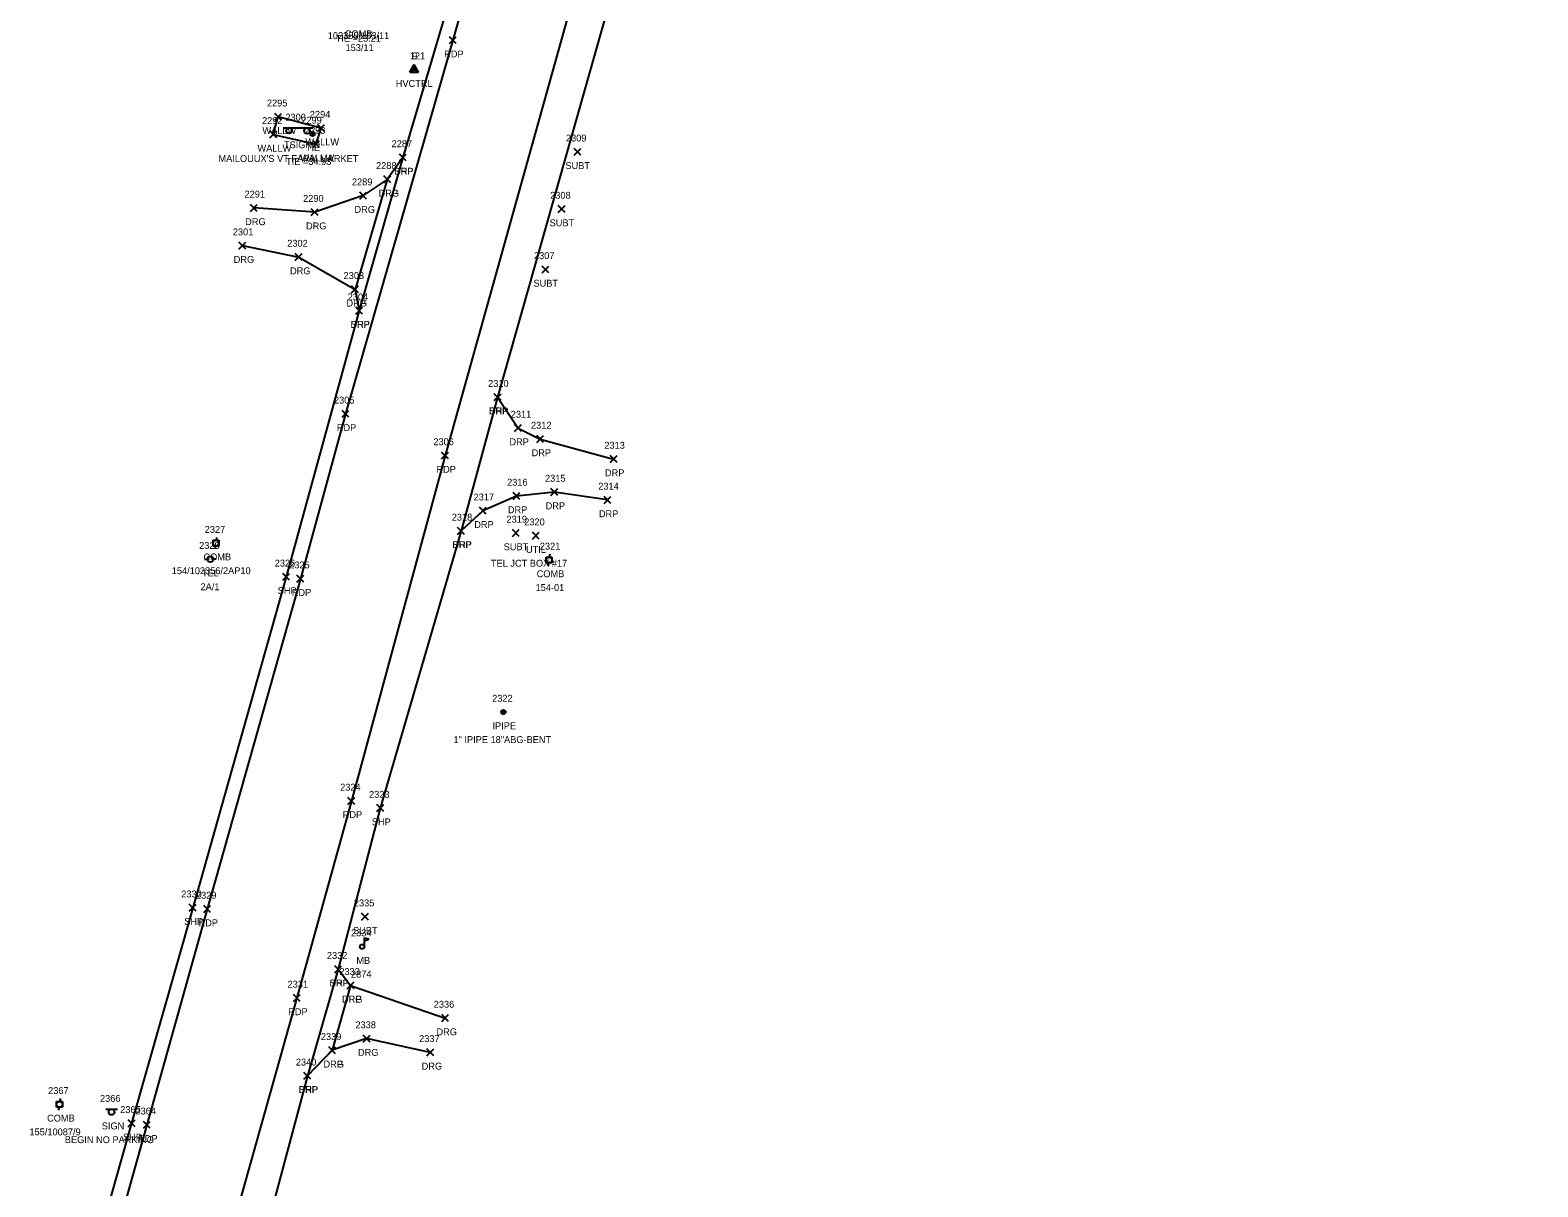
# Model space of a CAD drawing. Extents: x 1443071 to 1445292, y 614024 to 622563.
# Drawn here: x 1444316.5 to 1444754.4, y 621220.7 to 621556.7 of the extents above; entities that cross this region are included whole.
import ezdxf

# ---------------------------------------------------------------- set-up
doc = ezdxf.new("R2010")
doc.units = 0
for name, color, linetype in [('C_A', 7, 'Continuous'), ('C_C', 7, 'Continuous'), ('C_I', 7, 'Continuous'), ('CBP', 7, 'Continuous'), ('CPSM', 7, 'Continuous'), ('L_A', 7, 'Continuous'), ('L_C', 7, 'Continuous'), ('L_I', 7, 'Continuous'), ('L_TIC', 7, 'Continuous'), ('LMB', 7, 'Continuous'), ('LW', 7, 'Continuous'), ('M_A', 7, 'Continuous'), ('M_C', 7, 'Continuous'), ('M_I', 7, 'Continuous'), ('MPIP', 7, 'Continuous'), ('P_A', 7, 'Continuous'), ('P_I', 7, 'Continuous'), ('P_TIC', 7, 'Continuous'), ('PET', 7, 'Continuous'), ('PSP', 7, 'Continuous'), ('R_A', 7, 'Continuous'), ('R_I', 7, 'Continuous'), ('R_TIC', 7, 'Continuous'), ('RDG', 7, 'Continuous'), ('RDP', 7, 'Continuous'), ('S_A', 7, 'Continuous'), ('S_C', 7, 'Continuous'), ('S_I', 7, 'Continuous'), ('SSGN', 7, 'Continuous'), ('U_A', 7, 'Continuous'), ('U_C', 7, 'Continuous'), ('U_I', 7, 'Continuous'), ('U_TIC', 7, 'Continuous'), ('UDEFAULT', 7, 'Continuous'), ('UP', 7, 'Continuous')]:
    doc.layers.add(name, color=color, linetype=linetype)

msp = doc.modelspace()

# ---------------------------------------------------------------- linework, layer by layer
at = {"layer": 'CBP'}
for radius in [0.625, 0.0833]:
    msp.add_circle((1444398.54, 621526.59), radius, dxfattribs=at)
at = {"layer": 'CPSM'}
for p, q in [((1444426.77, 621544.56), (1444428.02, 621546.72)), ((1444426.77, 621544.56), (1444428.02, 621545.28)), ((1444426.8, 621544.55), (1444428.05, 621546.72)), ((1444426.8, 621544.55), (1444428.05, 621545.27)), ((1444429.27, 621544.56), (1444428.02, 621546.72)), ((1444428.02, 621545.28), (1444428.02, 621546.72)), ((1444428.02, 621545.28), (1444428.02, 621545.28)), ((1444428.02, 621545.28), (1444429.27, 621544.56)), ((1444429.3, 621544.55), (1444428.05, 621546.72)), ((1444428.05, 621545.27), (1444428.05, 621546.72)), ((1444428.05, 621545.27), (1444428.05, 621545.27)), ((1444428.05, 621545.27), (1444429.3, 621544.55)), ((1444426.77, 621544.56), (1444429.27, 621544.56)), ((1444426.8, 621544.55), (1444429.3, 621544.55))]:
    msp.add_line(p, q, dxfattribs=at)
at = {"layer": 'L_TIC'}
for points in [[(1444387.57, 621530.57), (1444389.57, 621532.57)], [(1444389.57, 621530.57), (1444387.57, 621532.57)], [(1444387.57, 621530.57), (1444389.57, 621532.57)], [(1444389.57, 621530.57), (1444387.57, 621532.57)], [(1444386.14, 621525.46), (1444388.14, 621527.46)], [(1444388.14, 621525.46), (1444386.14, 621527.46)], [(1444386.14, 621525.46), (1444388.14, 621527.46)], [(1444388.14, 621525.46), (1444386.14, 621527.46)], [(1444400.03, 621527.29), (1444402.03, 621529.29)], [(1444402.03, 621527.29), (1444400.03, 621529.29)], [(1444398.59, 621522.64), (1444400.59, 621524.64)], [(1444400.59, 621522.64), (1444398.59, 621524.64)]]:
    msp.add_lwpolyline(points, dxfattribs=at)
at = {"layer": 'LMB'}
for p, q in [((1444413.63, 621293.12), (1444414.92, 621292.74)), ((1444413.63, 621290.53), (1444413.63, 621293.12)), ((1444413.63, 621292.22), (1444414.91, 621292.73)), ((1444412.98, 621290.52), (1444412.98, 621290.52))]:
    msp.add_line(p, q, dxfattribs=at)
msp.add_circle((1444412.98, 621290.52), 0.656, dxfattribs=at)
at = {"layer": 'LW'}
for points in [[(1444387.14, 621526.46), (1444399.59, 621523.64), (1444401.03, 621528.29), (1444388.57, 621531.57)], [(1444387.14, 621526.46), (1444388.57, 621531.57)]]:
    msp.add_lwpolyline(points, dxfattribs=at)
at = {"layer": 'MPIP'}
for radius in [0.625, 0.0833]:
    msp.add_circle((1444453.98, 621358.66), radius, dxfattribs=at)
at = {"layer": 'P_TIC'}
for points in [[(1444438.29, 621552.82), (1444440.29, 621554.82)], [(1444440.29, 621552.82), (1444438.29, 621554.82)], [(1444423.77, 621518.75), (1444425.77, 621520.75)], [(1444425.77, 621518.75), (1444423.77, 621520.75)], [(1444411.09, 621474.26), (1444413.09, 621476.26)], [(1444413.09, 621474.26), (1444411.09, 621476.26)], [(1444451.32, 621449.13), (1444453.32, 621451.13)], [(1444453.32, 621449.13), (1444451.32, 621451.13)], [(1444407.11, 621444.28), (1444409.11, 621446.28)], [(1444409.11, 621444.28), (1444407.11, 621446.28)], [(1444436.04, 621432.18), (1444438.04, 621434.18)], [(1444438.04, 621432.18), (1444436.04, 621434.18)], [(1444440.68, 621410.27), (1444442.68, 621412.27)], [(1444442.68, 621410.27), (1444440.68, 621412.27)], [(1444389.88, 621396.93), (1444391.88, 621398.93)], [(1444391.88, 621396.93), (1444389.88, 621398.93)], [(1444394.03, 621396.39), (1444396.03, 621398.39)], [(1444396.03, 621396.39), (1444394.03, 621398.39)], [(1444408.83, 621331.84), (1444410.83, 621333.84)], [(1444410.83, 621331.84), (1444408.83, 621333.84)], [(1444417.22, 621329.76), (1444419.22, 621331.76)], [(1444419.22, 621329.76), (1444417.22, 621331.76)], [(1444362.76, 621300.82), (1444364.76, 621302.82)], [(1444364.76, 621300.82), (1444362.76, 621302.82)], [(1444366.96, 621300.44), (1444368.96, 621302.44)], [(1444368.96, 621300.44), (1444366.96, 621302.44)], [(1444404.98, 621282.95), (1444406.98, 621284.95)], [(1444406.98, 621282.95), (1444404.98, 621284.95)], [(1444392.99, 621274.61), (1444394.99, 621276.61)], [(1444394.99, 621274.61), (1444392.99, 621276.61)], [(1444396.04, 621251.99), (1444398.04, 621253.99)], [(1444398.04, 621251.99), (1444396.04, 621253.99)], [(1444344.99, 621238.2), (1444346.99, 621240.2)], [(1444346.99, 621238.2), (1444344.99, 621240.2)], [(1444349.41, 621237.76), (1444351.41, 621239.76)], [(1444351.41, 621237.76), (1444349.41, 621239.76)]]:
    msp.add_lwpolyline(points, dxfattribs=at)
at = {"layer": 'PET'}
for points in [[(1444754.44, 622544.13), (1444741.07, 622497.37), (1444724.21, 622436.63), (1444710.62, 622388.87), (1444697.45, 622342.15), (1444675, 622264.13), (1444650.85, 622183.92), (1444630.28, 622116), (1444610.88, 622049.25), (1444594.96, 621996.24), (1444563.37, 621884.27), (1444533.4, 621779.05), (1444495.09, 621640.86), (1444437.04, 621433.18), (1444409.83, 621332.84), (1444393.99, 621275.61), (1444360.23, 621155.32)], [(1444707.59, 622509.11), (1444700.19, 622484.07), (1444679.05, 622409.28), (1444655.77, 622327.83), (1444650.07, 622306.66), (1444636.13, 622255.68), (1444623.55, 622208.8), (1444606.26, 622146.53), (1444595.29, 622106.04), (1444582.56, 622060.23), (1444534.43, 621893.79), (1444481.57, 621704.27), (1444439.29, 621553.82), (1444408.11, 621445.28), (1444395.03, 621397.39), (1444367.96, 621301.44), (1444350.41, 621238.76), (1444319.14, 621126.97)]]:
    msp.add_lwpolyline(points, dxfattribs=at)
at = {"layer": 'PSP'}
for points in [[(1444703.05, 622509.58), (1444696.35, 622485.04), (1444679.96, 622426.95), (1444670.67, 622398.4), (1444651.65, 622328.99), (1444645.77, 622309.01), (1444600.31, 622147.99), (1444589.19, 622108.06), (1444575.49, 622063.15), (1444529.28, 621895.39), (1444476.53, 621706.36), (1444455.46, 621630.82), (1444442.09, 621578.45), (1444424.77, 621519.75), (1444412.09, 621475.26), (1444390.88, 621397.93), (1444363.76, 621301.82), (1444345.99, 621239.2), (1444324.65, 621163.68)], [(1444745.15, 622495.54), (1444738.65, 622472.69), (1444728.21, 622436.2), (1444714.89, 622387.13), (1444701.45, 622339.69), (1444679.77, 622260.17), (1444671.12, 622229.57), (1444657.52, 622182.26), (1444644.19, 622133.53), (1444626.95, 622072.43), (1444608.5, 622007.83), (1444599.1, 621977.5), (1444572.99, 621881.76), (1444551.74, 621805.05), (1444541.41, 621769.53), (1444519.46, 621688.51), (1444505.68, 621638.77), (1444452.32, 621450.13), (1444441.68, 621411.27), (1444418.22, 621330.76), (1444405.98, 621283.95), (1444397.04, 621252.99), (1444383.69, 621203.04)]]:
    msp.add_lwpolyline(points, dxfattribs=at)
at = {"layer": 'R_TIC'}
for points in [[(1444423.77, 621518.75), (1444425.77, 621520.75)], [(1444425.77, 621518.75), (1444423.77, 621520.75)], [(1444419.25, 621512.39), (1444421.25, 621514.39)], [(1444421.25, 621512.39), (1444419.25, 621514.39)], [(1444419.25, 621512.39), (1444421.25, 621514.39)], [(1444421.25, 621512.39), (1444419.25, 621514.39)], [(1444380.49, 621504.1), (1444382.49, 621506.1)], [(1444382.49, 621504.1), (1444380.49, 621506.1)], [(1444412.25, 621507.67), (1444414.25, 621509.67)], [(1444414.25, 621507.67), (1444412.25, 621509.67)], [(1444398.17, 621502.87), (1444400.17, 621504.87)], [(1444400.17, 621502.87), (1444398.17, 621504.87)], [(1444377.17, 621493.14), (1444379.17, 621495.14)], [(1444379.17, 621493.14), (1444377.17, 621495.14)], [(1444393.54, 621489.83), (1444395.54, 621491.83)], [(1444395.54, 621489.83), (1444393.54, 621491.83)], [(1444409.91, 621480.45), (1444411.91, 621482.45)], [(1444411.91, 621480.45), (1444409.91, 621482.45)], [(1444409.91, 621480.45), (1444411.91, 621482.45)], [(1444411.91, 621480.45), (1444409.91, 621482.45)], [(1444411.09, 621474.26), (1444413.09, 621476.26)], [(1444413.09, 621474.26), (1444411.09, 621476.26)], [(1444451.32, 621449.13), (1444453.32, 621451.13)], [(1444453.32, 621449.13), (1444451.32, 621451.13)], [(1444457.25, 621440.16), (1444459.25, 621442.16)], [(1444459.25, 621440.16), (1444457.25, 621442.16)], [(1444463.68, 621436.97), (1444465.68, 621438.97)], [(1444465.68, 621436.97), (1444463.68, 621438.97)], [(1444484.99, 621431.15), (1444486.99, 621433.15)], [(1444486.99, 621431.15), (1444484.99, 621433.15)], [(1444456.8, 621420.42), (1444458.8, 621422.42)], [(1444458.8, 621420.42), (1444456.8, 621422.42)], [(1444467.77, 621421.57), (1444469.77, 621423.57)], [(1444469.77, 621421.57), (1444467.77, 621423.57)], [(1444447.02, 621416.13), (1444449.02, 621418.13)], [(1444449.02, 621416.13), (1444447.02, 621418.13)], [(1444483.23, 621419.26), (1444485.23, 621421.26)], [(1444485.23, 621419.26), (1444483.23, 621421.26)], [(1444440.68, 621410.27), (1444442.68, 621412.27)], [(1444442.68, 621410.27), (1444440.68, 621412.27)], [(1444404.98, 621282.95), (1444406.98, 621284.95)], [(1444406.98, 621282.95), (1444404.98, 621284.95)], [(1444408.61, 621278.27), (1444410.61, 621280.27)], [(1444410.61, 621278.27), (1444408.61, 621280.27)], [(1444408.61, 621278.27), (1444410.61, 621280.27)], [(1444410.61, 621278.27), (1444408.61, 621280.27)], [(1444436.06, 621268.77), (1444438.06, 621270.77)], [(1444438.06, 621268.77), (1444436.06, 621270.77)], [(1444413.27, 621262.8), (1444415.27, 621264.8)], [(1444415.27, 621262.8), (1444413.27, 621264.8)], [(1444403.24, 621259.4), (1444405.24, 621261.4)], [(1444405.24, 621259.4), (1444403.24, 621261.4)], [(1444403.24, 621259.4), (1444405.24, 621261.4)], [(1444405.24, 621259.4), (1444403.24, 621261.4)], [(1444431.76, 621258.8), (1444433.76, 621260.8)], [(1444433.76, 621258.8), (1444431.76, 621260.8)], [(1444396.04, 621251.99), (1444398.04, 621253.99)], [(1444398.04, 621251.99), (1444396.04, 621253.99)]]:
    msp.add_lwpolyline(points, dxfattribs=at)
at = {"layer": 'RDG'}
for points in [[(1444420.25, 621513.39), (1444413.25, 621508.67), (1444399.17, 621503.87), (1444381.49, 621505.1)], [(1444378.17, 621494.14), (1444394.54, 621490.83), (1444410.91, 621481.45)], [(1444409.61, 621279.27), (1444437.06, 621269.77)], [(1444432.76, 621259.8), (1444414.27, 621263.8), (1444404.24, 621260.4)]]:
    msp.add_lwpolyline(points, dxfattribs=at)
at = {"layer": 'RDP'}
for points in [[(1444424.77, 621519.75), (1444420.25, 621513.39), (1444410.91, 621481.45), (1444412.09, 621475.26)], [(1444452.32, 621450.13), (1444458.25, 621441.16), (1444464.68, 621437.97), (1444485.99, 621432.15)], [(1444484.23, 621420.26), (1444468.77, 621422.57), (1444457.8, 621421.42), (1444448.02, 621417.13), (1444441.68, 621411.27)], [(1444405.98, 621283.95), (1444409.61, 621279.27), (1444404.24, 621260.4), (1444397.04, 621252.99)]]:
    msp.add_lwpolyline(points, dxfattribs=at)
at = {"layer": 'SSGN'}
for p, q in [((1444390.07, 621528.37), (1444398.66, 621528.37)), ((1444394.09, 621527.47), (1444394.09, 621527.47)), ((1444338.55, 621243.3), (1444341.88, 621243.3)), ((1444340.19, 621242.46), (1444340.19, 621242.46))]:
    msp.add_line(p, q, dxfattribs=at)
for centre in [(1444391.73, 621527.54), (1444396.94, 621527.47), (1444340.19, 621242.46)]:
    msp.add_circle(centre, 0.833, dxfattribs=at)
at = {"layer": 'U_TIC'}
for points in [[(1444474.5, 621520.4), (1444476.5, 621522.4)], [(1444476.5, 621520.4), (1444474.5, 621522.4)], [(1444469.91, 621503.77), (1444471.91, 621505.77)], [(1444471.91, 621503.77), (1444469.91, 621505.77)], [(1444465.21, 621486.23), (1444467.21, 621488.23)], [(1444467.21, 621486.23), (1444465.21, 621488.23)], [(1444456.58, 621409.67), (1444458.58, 621411.67)], [(1444458.58, 621409.67), (1444456.58, 621411.67)], [(1444412.81, 621298.21), (1444414.81, 621300.21)], [(1444414.81, 621298.21), (1444412.81, 621300.21)]]:
    msp.add_lwpolyline(points, dxfattribs=at)
at = {"layer": 'UDEFAULT'}
for points in [[(1444462.39, 621408.89), (1444464.39, 621410.89)], [(1444464.39, 621408.89), (1444462.39, 621410.89)]]:
    msp.add_lwpolyline(points, dxfattribs=at)
at = {"layer": 'UP'}
for p, q in [((1444370.75, 621409.39), (1444370.5, 621408.56)), ((1444369.66, 621406.89), (1444369.66, 621408.56)), ((1444369.66, 621408.56), (1444371.33, 621408.56)), ((1444371.33, 621406.89), (1444369.66, 621406.89)), ((1444370.25, 621406.06), (1444370.5, 621406.89)), ((1444370.5, 621407.72), (1444370.5, 621407.72)), ((1444371.33, 621408.56), (1444371.33, 621406.89)), ((1444367.21, 621403.04), (1444368.04, 621403.04)), ((1444368.87, 621403.05), (1444368.87, 621403.05)), ((1444370.54, 621403.05), (1444369.7, 621403.05)), ((1444369.7, 621403.05), (1444369.7, 621403.05)), ((1444370.54, 621403.05), (1444370.54, 621403.05)), ((1444466.43, 621402), (1444466.43, 621403.67)), ((1444466.43, 621403.67), (1444468.1, 621403.67)), ((1444468.1, 621402), (1444466.43, 621402)), ((1444467.01, 621401.17), (1444467.26, 621402)), ((1444467.51, 621404.5), (1444467.26, 621403.67)), ((1444467.26, 621402.83), (1444467.26, 621402.83)), ((1444468.1, 621403.67), (1444468.1, 621402)), ((1444324.23, 621243.87), (1444324.23, 621245.53)), ((1444324.23, 621245.53), (1444325.9, 621245.53)), ((1444325.9, 621243.87), (1444324.23, 621243.87)), ((1444324.81, 621243.03), (1444325.06, 621243.87)), ((1444325.31, 621246.37), (1444325.06, 621245.53)), ((1444325.06, 621244.7), (1444325.06, 621244.7)), ((1444325.9, 621245.53), (1444325.9, 621243.87))]:
    msp.add_line(p, q, dxfattribs=at)
for centre in [(1444370.5, 621407.72), (1444368.87, 621403.05), (1444467.26, 621402.83), (1444325.06, 621244.7)]:
    msp.add_circle(centre, 0.833, dxfattribs=at)

# ---------------------------------------------------------------- texts
at = {"layer": 'C_A'}
for s, p in [('HVCTRL', (1444422.72, 621540.28)), ('HVCTRL', (1444422.74, 621540.27)), ('TIE', (1444396.62, 621521.59))]:
    msp.add_text(s, height=2, dxfattribs=at).set_placement(p)
at = {"layer": 'C_C'}
for s, p in [('TIE =23.21', (1444405.26, 621553.38)), ('TIE =34.93', (1444390.87, 621517.59))]:
    msp.add_text(s, height=2, dxfattribs=at).set_placement(p)
at = {"layer": 'C_I'}
for s, p in [('121', (1444426.8, 621548.28)), ('9', (1444427.48, 621548.27)), ('2299', (1444395.27, 621529.59))]:
    msp.add_text(s, height=2, dxfattribs=at).set_placement(p)
at = {"layer": 'L_A'}
for s, p in [('WALLW', (1444383.99, 621526.57)), ('WALLW', (1444383.99, 621526.57)), ('WALLW', (1444382.56, 621521.46)), ('WALLW', (1444382.56, 621521.46)), ('WALLW', (1444396.45, 621523.29)), ('WALLW', (1444395.01, 621518.64)), ('MB', (1444411.28, 621285.52))]:
    msp.add_text(s, height=2, dxfattribs=at).set_placement(p)
at = {"layer": 'L_C'}
msp.add_text('2874', height=2, dxfattribs=at).set_placement((1444409.72, 621281.52))
at = {"layer": 'L_I'}
for s, p in [('2295', (1444385.31, 621534.57)), ('2295', (1444385.31, 621534.57)), ('2294', (1444397.77, 621531.29)), ('2292', (1444383.88, 621529.46)), ('2292', (1444383.88, 621529.46)), ('2293', (1444396.33, 621526.64)), ('2334', (1444409.72, 621293.52))]:
    msp.add_text(s, height=2, dxfattribs=at).set_placement(p)
at = {"layer": 'M_A'}
msp.add_text('IPIPE', height=2, dxfattribs=at).set_placement((1444450.82, 621353.66))
at = {"layer": 'M_C'}
msp.add_text('1" IPIPE 18"ABG-BENT', height=2, dxfattribs=at).set_placement((1444439.49, 621349.66))
at = {"layer": 'M_I'}
msp.add_text('2322', height=2, dxfattribs=at).set_placement((1444450.72, 621361.66))
at = {"layer": 'P_A'}
for s, p in [('RDP', (1444436.78, 621548.82)), ('SHP', (1444422.31, 621514.75)), ('SHP', (1444409.63, 621470.26)), ('SHP', (1444449.86, 621445.13)), ('RDP', (1444405.6, 621440.28)), ('RDP', (1444434.53, 621428.18)), ('SHP', (1444439.21, 621406.27)), ('SHP', (1444388.42, 621392.93)), ('RDP', (1444392.52, 621392.39)), ('RDP', (1444407.32, 621327.84)), ('SHP', (1444415.76, 621325.76)), ('SHP', (1444361.3, 621296.82)), ('RDP', (1444365.45, 621296.44)), ('SHP', (1444403.52, 621278.95)), ('RDP', (1444391.48, 621270.61)), ('SHP', (1444394.58, 621247.99)), ('SHP', (1444343.52, 621234.2)), ('RDP', (1444347.9, 621233.76))]:
    msp.add_text(s, height=2, dxfattribs=at).set_placement(p)
at = {"layer": 'P_I'}
for s, p in [('2287', (1444421.51, 621522.75)), ('2304', (1444408.76, 621478.26)), ('2310', (1444449.54, 621453.13)), ('2305', (1444404.77, 621448.28)), ('2306', (1444433.65, 621436.18)), ('2318', (1444438.98, 621414.27)), ('2326', (1444387.57, 621400.93)), ('2325', (1444391.77, 621400.39)), ('2324', (1444406.57, 621335.84)), ('2323', (1444414.96, 621333.76)), ('2330', (1444360.42, 621304.82)), ('2329', (1444364.69, 621304.44)), ('2332', (1444402.72, 621286.95)), ('2331', (1444391.3, 621278.61)), ('2340', (1444393.7, 621255.99)), ('2365', (1444342.68, 621242.2)), ('2364', (1444347.11, 621241.76))]:
    msp.add_text(s, height=2, dxfattribs=at).set_placement(p)
at = {"layer": 'R_A'}
for s, p in [('DRP', (1444422.26, 621514.75)), ('DRG', (1444417.73, 621508.39)), ('DRP', (1444417.73, 621508.39)), ('DRG', (1444410.74, 621503.67)), ('DRG', (1444378.98, 621500.1)), ('DRG', (1444396.65, 621498.87)), ('DRG', (1444375.66, 621489.14)), ('DRG', (1444392.02, 621485.83)), ('DRG', (1444408.4, 621476.45)), ('DRP', (1444408.4, 621476.45)), ('DRP', (1444409.58, 621470.26)), ('DRP', (1444449.81, 621445.13)), ('DRP', (1444455.74, 621436.16)), ('DRP', (1444462.17, 621432.97)), ('DRP', (1444483.48, 621427.15)), ('DRP', (1444455.29, 621416.42)), ('DRP', (1444466.26, 621417.57)), ('DRP', (1444445.51, 621412.13)), ('DRP', (1444481.72, 621415.26)), ('DRP', (1444439.16, 621406.27)), ('DRP', (1444403.47, 621278.95)), ('DRG', (1444407.1, 621274.27)), ('DRP', (1444407.1, 621274.27)), ('DRG', (1444434.55, 621264.77)), ('DRG', (1444411.75, 621258.8)), ('DRG', (1444401.73, 621255.4)), ('DRP', (1444401.73, 621255.4)), ('DRG', (1444430.25, 621254.8)), ('DRP', (1444394.53, 621247.99))]:
    msp.add_text(s, height=2, dxfattribs=at).set_placement(p)
at = {"layer": 'R_I'}
for s, p in [('2287', (1444421.51, 621522.75)), ('2288', (1444416.99, 621516.39)), ('2288', (1444416.99, 621516.39)), ('2291', (1444378.8, 621508.1)), ('2289', (1444409.99, 621511.67)), ('2290', (1444395.82, 621506.87)), ('2301', (1444375.4, 621497.14)), ('2302', (1444391.2, 621493.83)), ('2303', (1444407.57, 621484.45)), ('2303', (1444407.57, 621484.45)), ('2304', (1444408.76, 621478.26)), ('2310', (1444449.54, 621453.13)), ('2311', (1444456.13, 621444.16)), ('2312', (1444461.99, 621440.97)), ('2313', (1444483.3, 621435.15)), ('2315', (1444466.07, 621425.57)), ('2317', (1444445.33, 621420.13)), ('2316', (1444455.05, 621424.42)), ('2314', (1444481.54, 621423.26)), ('2318', (1444438.98, 621414.27)), ('2332', (1444402.72, 621286.95)), ('2333', (1444406.35, 621282.27)), ('2333', (1444406.35, 621282.27)), ('2336', (1444433.75, 621272.77)), ('2339', (1444400.97, 621263.4)), ('2339', (1444400.97, 621263.4)), ('2338', (1444411.01, 621266.8)), ('2337', (1444429.5, 621262.8)), ('2340', (1444393.7, 621255.99))]:
    msp.add_text(s, height=2, dxfattribs=at).set_placement(p)
at = {"layer": 'S_A'}
for s, p in [('TSIGN', (1444390.26, 621522.45)), ('SIGN', (1444337.33, 621237.44))]:
    msp.add_text(s, height=2, dxfattribs=at).set_placement(p)
at = {"layer": 'S_C'}
for s, p in [("MAILOUUX'S VT FARM MARKET", (1444371.24, 621518.45)), ('BEGIN NO PARKING', (1444326.61, 621233.44))]:
    msp.add_text(s, height=2, dxfattribs=at).set_placement(p)
at = {"layer": 'S_I'}
for s, p in [('2300', (1444390.66, 621530.45)), ('2366', (1444336.81, 621245.44))]:
    msp.add_text(s, height=2, dxfattribs=at).set_placement(p)
at = {"layer": 'U_A'}
for s, p in [('COMB', (1444407.95, 621554.66)), ('SUBT', (1444472, 621516.4)), ('SUBT', (1444467.41, 621499.77)), ('SUBT', (1444462.71, 621482.23)), ('COMB', (1444366.88, 621402.72)), ('SUBT', (1444454.07, 621405.67)), ('UTIL', (1444460.55, 621404.89)), ('TEL', (1444366.43, 621398.05)), ('COMB', (1444463.65, 621397.83)), ('SUBT', (1444410.31, 621294.21)), ('COMB', (1444321.45, 621239.7))]:
    msp.add_text(s, height=2, dxfattribs=at).set_placement(p)
at = {"layer": 'U_C'}
for s, p in [('102355/153/11', (1444402.99, 621554.15)), ('153/11', (1444408.13, 621550.66)), ('154/102356/2AP10', (1444357.67, 621398.72)), ('TEL JCT BOX #17', (1444450.36, 621400.89)), ('2A/1', (1444366.02, 621394.05)), ('154-01', (1444463.34, 621393.83)), ('155/10087/9', (1444316.33, 621235.7))]:
    msp.add_text(s, height=2, dxfattribs=at).set_placement(p)
at = {"layer": 'U_I'}
for s, p in [('2309', (1444472.16, 621524.4)), ('2308', (1444467.57, 621507.77)), ('2307', (1444462.87, 621490.23)), ('2319', (1444454.88, 621413.67)), ('2320', (1444460.04, 621412.89)), ('2327', (1444367.24, 621410.72)), ('2328', (1444365.61, 621406.05)), ('2321', (1444464.57, 621405.83)), ('2335', (1444410.55, 621302.21)), ('2367', (1444321.75, 621247.7))]:
    msp.add_text(s, height=2, dxfattribs=at).set_placement(p)

doc.saveas('drawing.dxf')
